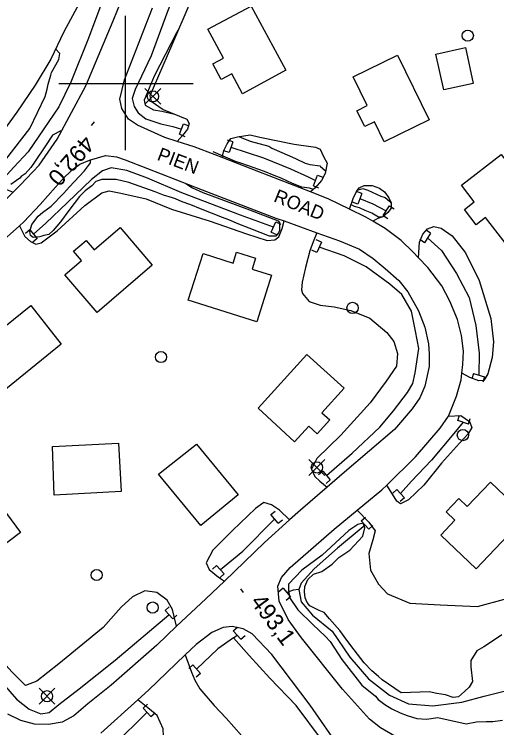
# Model space of a CAD drawing. Extents: x 642515 to 647219, y 6080136 to 6084356.
# Drawn here: x 643780.2 to 643866.3, y 6081485.1 to 6081612.4 of the extents above; entities that cross this region are included whole.
import ezdxf

# ---------------------------------------------------------------- set-up
doc = ezdxf.new("R2010")
doc.units = 0
for name, color, linetype in [('Level 19', 7, 'Continuous'), ('Level 2', 7, 'Continuous'), ('Level 21', 7, 'Continuous'), ('Level 26', 7, 'Continuous'), ('Level 3', 7, 'Continuous'), ('Level 31', 7, 'Continuous'), ('Level 36', 7, 'Continuous'), ('Level 4', 7, 'Continuous'), ('Level 61', 7, 'Continuous')]:
    doc.layers.add(name, color=color, linetype=linetype)

msp = doc.modelspace()

# ---------------------------------------------------------------- linework, layer by layer
at = {"layer": 'Level 19'}
for points in [[(643831.06, 6081654.31), (643831.99, 6081651.64), (643832.31, 6081649.67), (643832.1, 6081648.48), (643831.21, 6081647.66), (643829.54, 6081647.7), (643825.17, 6081648.15), (643822.52, 6081648.29), (643821.82, 6081647.76), (643820.73, 6081646.29), (643818.93, 6081641.16), (643816.67, 6081632), (643814.94, 6081625.17), (643813.39, 6081619.86), (643811.57, 6081614.41), (643808.28, 6081606.76), (643804.43, 6081597.87), (643804.66, 6081596.92), (643806.77, 6081595.44), (643811, 6081593.71), (643811.46, 6081592.93), (643811.16, 6081591.9), (643810.23, 6081590.75), (643809.32, 6081589.72)], [(643799.39, 6081615.12), (643798.24, 6081616.05), (643796.81, 6081616.85), (643795.49, 6081617.32), (643793.8, 6081617.29), (643792.68, 6081616.45), (643791.81, 6081614.33), (643789.04, 6081609.27), (643786.74, 6081604.39), (643783.98, 6081599.77), (643780.67, 6081594.95), (643777.33, 6081590.45), (643775.5, 6081588.27), (643773.83, 6081586.1), (643773.65, 6081585.12), (643774.07, 6081584.3), (643775.32, 6081583.05), (643777.33, 6081581.97), (643778.54, 6081581.29), (643780.02, 6081580.68)], [(643817.3, 6081586.84), (643817.62, 6081588.11), (643818.19, 6081589.28), (643818.87, 6081590.23), (643820.08, 6081590.57), (643822.29, 6081590.9), (643824.06, 6081590.5), (643830.15, 6081589.25), (643833.96, 6081588.71), (643834.81, 6081588.35), (643835.38, 6081587.05), (643836.04, 6081585.87), (643835.7, 6081584.01), (643835.02, 6081582.75), (643833.91, 6081581.45), (643833.11, 6081580.71)], [(643840.02, 6081577.63), (643840.68, 6081579.51), (643841.28, 6081580.8), (643841.79, 6081581.42), (643842.65, 6081581.88), (643844.08, 6081581.84), (643845.42, 6081581.38), (643846.27, 6081580.71), (643847.07, 6081579.63), (643847.45, 6081578.77), (643847.47, 6081577.81), (643846.9, 6081577.02), (643845.98, 6081576.27), (643845.09, 6081575.95), (643844.18, 6081575.49)], [(643781.14, 6081574.67), (643782.11, 6081572.76), (643783.14, 6081571.86), (643784.06, 6081571.36), (643785.05, 6081571.62), (643787.89, 6081573.75), (643792.79, 6081578.31), (643795.87, 6081580.53), (643797.18, 6081580.9), (643799.22, 6081580.47), (643803.73, 6081579.48), (643808.29, 6081577.61), (643815.2, 6081575.48), (643821.69, 6081573.21), (643825.35, 6081572.04), (643826.72, 6081572.13), (643827.45, 6081572.71), (643828.04, 6081574.16), (643828.37, 6081575.53)], [(643852.38, 6081568.97), (643852.52, 6081571.73), (643853.11, 6081573.18), (643853.94, 6081574.12), (643855.12, 6081574.52), (643856.39, 6081574.24), (643858.37, 6081572.88), (643860.75, 6081569.81), (643863.21, 6081564.93), (643865.24, 6081558.09), (643865.71, 6081553.97), (643865.49, 6081551.13), (643864.72, 6081548.26), (643864.03, 6081547.04), (643863.1, 6081547.02), (643861.49, 6081547.6), (643860.08, 6081548.39)], [(643834.23, 6081573.41), (643833.53, 6081571.83), (643832.95, 6081570.22), (643832.22, 6081567.23), (643831.58, 6081564.6), (643831.47, 6081563.26), (643831.64, 6081562.59), (643832.82, 6081561.17), (643834.8, 6081560.5), (643837.32, 6081560.18), (643840.31, 6081559.53), (643843.66, 6081558.18), (643846.73, 6081555.64), (643847.97, 6081554.03), (643848.59, 6081551.89), (643848.42, 6081549.63), (643846.58, 6081546.92), (643843.74, 6081543.06), (643838.47, 6081537.31), (643834.2, 6081533.12), (643833.28, 6081531.2), (643833.84, 6081529.95), (643834.75, 6081529.08), (643836.08, 6081528.04)], [(643857.71, 6081540.71), (643859.89, 6081540.78), (643861.45, 6081539.71), (643861.88, 6081538.65), (643861.23, 6081537.56), (643859.65, 6081535.84), (643856.46, 6081532.28), (643853.29, 6081528.4), (643850.6, 6081525.76), (643849.15, 6081525.06), (643848.48, 6081525.5), (643847.71, 6081526.78), (643846.68, 6081528.4)], [(643829.34, 6081522.18), (643827.53, 6081523.91), (643826.1, 6081524.87), (643824.78, 6081525.26), (643823.24, 6081524.19), (643819.15, 6081520.29), (643815.67, 6081516.76), (643814.45, 6081514.5), (643815.01, 6081513.33), (643816.68, 6081511.94), (643817.71, 6081511.27)], [(643841.43, 6081523.93), (643843.51, 6081521.8), (643844.62, 6081520.22), (643844.2, 6081518.62), (643843.52, 6081516.2), (643843.79, 6081513.23), (643845.21, 6081510.71), (643846.81, 6081509), (643850.79, 6081507.33), (643856.21, 6081507.04), (643862.89, 6081506.72), (643867.72, 6081508.01)], [(643809.2, 6081503.18), (643808.48, 6081506.16), (643807.53, 6081507.83), (643805.66, 6081509.24), (643803.55, 6081509.5), (643801.32, 6081508.42), (643799.27, 6081506.59), (643796.08, 6081502.96), (643788.17, 6081496.5), (643784.22, 6081493.38), (643782.22, 6081492.64), (643779.84, 6081495.02), (643777.02, 6081498.1), (643774.62, 6081499.75), (643773.47, 6081499.48), (643770.5, 6081497.2)], [(643810.74, 6081498.1), (643811.87, 6081495), (643812.45, 6081493.58), (643813.36, 6081492.03), (643815.89, 6081489.05), (643818.06, 6081486.78), (643822.15, 6081482.13)], [(643782.93, 6081478.42), (643781.13, 6081477.13), (643780.07, 6081476.01), (643779.14, 6081474.26), (643778.59, 6081472.16), (643779.01, 6081470.22), (643779.99, 6081468.75), (643781.66, 6081467.29), (643783.9, 6081466.23), (643786.74, 6081466.46), (643789.98, 6081466.8), (643791.83, 6081467.44), (643795.32, 6081468.92), (643800.32, 6081470.59), (643801.97, 6081471.34), (643802.76, 6081472.16), (643803.66, 6081473.71), (643804.94, 6081476.98), (643806.46, 6081479.58), (643806.92, 6081482.27), (643806.79, 6081484.88), (643805.71, 6081487.26), (643804.04, 6081488.65), (643802.26, 6081490.08)]]:
    msp.add_lwpolyline(points, dxfattribs=at)
at = {"layer": 'Level 2'}
for points in [[(643809.7, 6081610.06), (643809.2, 6081609.08), (643805.18, 6081601.37), (643803.42, 6081597.11), (643803.6, 6081596.2), (643805.07, 6081595.37), (643806.57, 6081595.11), (643808.9, 6081594.57)], [(643778.72, 6081586.47), (643782.97, 6081592.02), (643785.76, 6081597.72), (643786.11, 6081599.07), (643786.25, 6081599.92), (643786.75, 6081601.52), (643786.87, 6081602.01), (643788.16, 6081604.35), (643788.33, 6081605.41), (643787.6, 6081606.22)], [(643788.62, 6081591.54), (643788.51, 6081591.62), (643787.07, 6081590.84), (643785.69, 6081588.74), (643783.97, 6081586.17), (643783.16, 6081585.07), (643782.15, 6081583.92), (643781.46, 6081583.47), (643781.2, 6081583.17), (643779.63, 6081582.06)], [(643820.29, 6081590.61), (643820.69, 6081590.45), (643822.3, 6081589.79), (643825.66, 6081588.88), (643826.17, 6081588.51), (643829.36, 6081587.16), (643830.52, 6081586.59), (643832.14, 6081585.85), (643832.97, 6081585.58), (643834.79, 6081585.34), (643834.83, 6081585.3), (643835.78, 6081584.47)], [(643833.59, 6081581.15), (643832.89, 6081581.35), (643831.51, 6081581.58), (643829.86, 6081582.2), (643827.86, 6081583.19), (643826.58, 6081583.63), (643824.88, 6081584.37), (643820.84, 6081585.79), (643819.7, 6081586.12), (643815.71, 6081587.86)], [(643810.82, 6081582.21), (643812.05, 6081581.43), (643813.88, 6081580.58), (643822.21, 6081577.51), (643827.3, 6081575.55), (643827.56, 6081575.25), (643827.58, 6081573.8), (643827.4, 6081573.43), (643826.92, 6081572.79), (643825.75, 6081572.84), (643824.1, 6081573.45), (643822.16, 6081574.25), (643820.3, 6081574.97), (643818.52, 6081575.7), (643817.4, 6081576.15), (643813.47, 6081577.7), (643811.74, 6081578.39), (643810.21, 6081578.97), (643808.97, 6081579.45), (643808.47, 6081579.66), (643806.83, 6081580.12), (643805.38, 6081580.71), (643800.68, 6081582.41), (643798.4, 6081582.9), (643795.86, 6081582.93), (643794.76, 6081582.54), (643794.09, 6081581.77), (643792.86, 6081580.88), (643791.84, 6081579.89), (643790.92, 6081578.66), (643789.96, 6081577.39), (643788.45, 6081575.4), (643787.15, 6081573.83), (643786.39, 6081573.13), (643785.48, 6081572.95), (643784.77, 6081572.67), (643783.61, 6081572.55), (643783.1, 6081572.92), (643782.98, 6081573.63), (643783.33, 6081574.9), (643784.48, 6081576.39), (643785.28, 6081577.04), (643786.81, 6081578.19), (643788.99, 6081580.43), (643790.08, 6081581.59), (643791.8, 6081583.47), (643792.77, 6081584.5), (643793.85, 6081585.9), (643793.83, 6081586.4)], [(643841.49, 6081581.05), (643841.56, 6081581.08), (643842.43, 6081581.3), (643843.33, 6081581.04), (643845.62, 6081579.94), (643846.4, 6081579.71), (643847.17, 6081579.04), (643847.45, 6081578.68)], [(643845.73, 6081576.18), (643845.23, 6081576.21), (643844.02, 6081576.9), (643842.86, 6081577.39), (643841.82, 6081577.84), (643840.92, 6081578.1), (643840.31, 6081578.44)], [(643835.51, 6081505.64), (643834.61, 6081505.98), (643832.94, 6081506.84), (643832.46, 6081507.41), (643832.16, 6081508.27), (643832, 6081509.31), (643832.1, 6081510.28), (643832.61, 6081511.56), (643833.64, 6081512.48), (643835.1, 6081512.94), (643836.94, 6081514.27), (643838.14, 6081515.47), (643840.1, 6081516.77), (643842.43, 6081519.26), (643842.77, 6081520.77), (643842.51, 6081521.6), (643841.52, 6081521.33), (643839.91, 6081520.26), (643835.18, 6081515.88), (643831.54, 6081513.18), (643829.13, 6081510.69), (643829.16, 6081509.69), (643829.34, 6081508.33), (643830.81, 6081506.13), (643833.49, 6081503.49), (643835.68, 6081501.42), (643836.59, 6081500.48), (643838.7, 6081497.28), (643842.23, 6081492.68), (643844.66, 6081490.71), (643845.14, 6081490.13), (643846.37, 6081489.21), (643847.59, 6081488.44), (643849.09, 6081487.74), (643850.33, 6081487.26), (643852.05, 6081486.73), (643853.79, 6081486.64), (643855.78, 6081486.93), (643860.89, 6081485.78), (643862.72, 6081486.14), (643864.44, 6081486.22), (643865.65, 6081486.22), (643867.32, 6081486.41)], [(643867.21, 6081501.66), (643865.55, 6081500.54), (643864.01, 6081499.55), (643862.74, 6081498.79), (643861.69, 6081497.07), (643861.72, 6081495.98), (643861.98, 6081493.34), (643861.41, 6081492.34), (643860.57, 6081491.56), (643859.51, 6081490.6), (643858.56, 6081490.46), (643857.16, 6081490.93), (643855.65, 6081491.19), (643854.26, 6081491.5), (643849.28, 6081491.33), (643845.87, 6081493.64), (643845.23, 6081494.21), (643844.03, 6081495.25), (643842.64, 6081496.69), (643840.88, 6081498.99), (643839.59, 6081500.72), (643838.31, 6081502.44), (643836.48, 6081504.49), (643835.51, 6081505.64)]]:
    msp.add_lwpolyline(points, dxfattribs=at)
at = {"layer": 'Level 21'}
for points in [[(643710.16, 6081521.04), (643716.3, 6081526.08), (643720.63, 6081529.63), (643725.84, 6081533.79), (643733.91, 6081540.23), (643740.4, 6081545.91), (643744.23, 6081549.26), (643747.02, 6081551.59), (643754.73, 6081558), (643758.17, 6081560.87), (643761.09, 6081563.4), (643771.97, 6081572.84), (643773.31, 6081574.14), (643780.02, 6081580.68), (643781.26, 6081581.89), (643784.65, 6081585.5), (643787.85, 6081590.11), (643792.99, 6081599.62), (643797.87, 6081611.24), (643799.39, 6081615.12)], [(643827.27, 6081510.34), (643827.89, 6081511.91), (643829.43, 6081513.67), (643837.32, 6081520.52), (643841.43, 6081523.93), (643845.8, 6081527.54), (643846.68, 6081528.4), (643851.82, 6081533.46), (643856.25, 6081538.52), (643857.71, 6081540.71), (643859.13, 6081544.23), (643859.95, 6081547.15), (643860.08, 6081548.39), (643860.25, 6081549.91), (643860.37, 6081552.3), (643860.03, 6081555.1), (643859.32, 6081557.92), (643857.97, 6081561.21), (643856.5, 6081563.94), (643854.03, 6081567.24), (643852.38, 6081568.97), (643851.43, 6081569.98), (643849.28, 6081572.01), (643846.43, 6081574.2), (643844.18, 6081575.49), (643842.95, 6081576.19), (643840.02, 6081577.63), (643836.24, 6081579.5), (643833.11, 6081580.71), (643823.86, 6081584.28), (643817.3, 6081586.84), (643812.35, 6081588.77), (643809.32, 6081589.72), (643807.07, 6081590.43), (643802.2, 6081592.65), (643800.6, 6081593.68), (643799.43, 6081595.62), (643799.07, 6081597.29), (643799.89, 6081600.73), (643804.86, 6081613.58)], [(643777.23, 6081571.2), (643781.14, 6081574.67), (643781.91, 6081575.36), (643784.85, 6081578.46), (643787.55, 6081581.55), (643789.28, 6081583.44), (643790.8, 6081584.83), (643791.92, 6081585.67), (643793.65, 6081586.35), (643796.5, 6081587.19), (643798.45, 6081586.99), (643800.01, 6081586.45), (643803.99, 6081584.86), (643813.76, 6081581.07), (643826.92, 6081576.05), (643828.37, 6081575.53), (643834.23, 6081573.41), (643838.25, 6081571.96), (643841.81, 6081570.5), (643844.26, 6081568.81), (643846.43, 6081567.06), (643848.84, 6081564.88), (643850.46, 6081562.85), (643852.38, 6081559.51), (643853.5, 6081556.56), (643854.14, 6081553.58), (643854.26, 6081551.81), (643854.24, 6081549.55), (643853.51, 6081546.03), (643852.6, 6081543.95), (643851.24, 6081541.97), (643848.05, 6081538.33), (643839.16, 6081530.68), (643836.08, 6081528.04), (643831.3, 6081523.94), (643829.34, 6081522.18), (643824.87, 6081518.15), (643817.71, 6081511.27), (643814.41, 6081508.1), (643809.2, 6081503.18), (643805.65, 6081499.82), (643797.5, 6081492.67), (643793.36, 6081489.33), (643790.84, 6081487.23), (643788.79, 6081486.08), (643786.36, 6081485.64), (643783.85, 6081485.71), (643781.4, 6081486.36), (643779.1, 6081487.53)], [(643872.1, 6081481.95), (643864.54, 6081481.16), (643857.81, 6081481.24), (643852.11, 6081482.07), (643848.14, 6081483.58), (643845.58, 6081485.06), (643843.63, 6081486.62), (643838.8, 6081491.99), (643831.46, 6081501.14), (643829.11, 6081504.41), (643827.52, 6081507.69), (643827.27, 6081510.34)], [(643838.53, 6081481.14), (643833.04, 6081489.12), (643826.2, 6081498.14), (643822.69, 6081501.82), (643821.06, 6081502.72), (643819.1, 6081503.15), (643817.5, 6081502.97), (643815.46, 6081502.1), (643812.66, 6081499.94), (643810.74, 6081498.1), (643804.17, 6081491.8), (643802.26, 6081490.08), (643795.65, 6081484.14)]]:
    msp.add_lwpolyline(points, dxfattribs=at)
at = {"layer": 'Level 26'}
for p, q in [((643809.72, 6081590.99), (643810.44, 6081592.89)), ((643810.44, 6081592.89), (643811.38, 6081592.51)), ((643809.72, 6081590.99), (643810.66, 6081590.63)), ((643819.23, 6081589.62), (643818.29, 6081589.96)), ((643819.23, 6081589.62), (643818.55, 6081587.72)), ((643818.55, 6081587.72), (643817.61, 6081588.06)), ((643833.62, 6081581.8), (643834.36, 6081583.68)), ((643834.36, 6081583.68), (643835.28, 6081583.32)), ((643833.62, 6081581.8), (643834.54, 6081581.44)), ((643842.26, 6081580.45), (643841.32, 6081580.81)), ((643842.26, 6081580.45), (643841.54, 6081578.55)), ((643841.54, 6081578.55), (643840.6, 6081578.91)), ((643846.06, 6081576.52), (643847.16, 6081578.22)), ((643847.16, 6081578.22), (643848, 6081577.68)), ((643846.06, 6081576.52), (643846.9, 6081575.98)), ((643826.08, 6081573.51), (643826.88, 6081575.37)), ((643826.88, 6081575.37), (643827.8, 6081574.97)), ((643783, 6081573.92), (643782.24, 6081573.3)), ((643783, 6081573.92), (643784.3, 6081572.38)), ((643826.08, 6081573.51), (643827, 6081573.11)), ((643854.52, 6081573.33), (643853.42, 6081571.63)), ((643854.52, 6081573.33), (643853.7, 6081573.87)), ((643784.3, 6081572.38), (643783.52, 6081571.74)), ((643835.02, 6081571.77), (643834.1, 6081572.17)), ((643835.02, 6081571.77), (643834.22, 6081569.91)), ((643853.42, 6081571.63), (643852.58, 6081572.19)), ((643834.22, 6081569.91), (643833.3, 6081570.31)), ((643862.18, 6081548.33), (643861.88, 6081547.37)), ((643862.18, 6081548.33), (643864.12, 6081547.73)), ((643864.12, 6081547.73), (643863.82, 6081546.77)), ((643859.35, 6081539.93), (643859.65, 6081540.89)), ((643861.25, 6081539.29), (643859.35, 6081539.93)), ((643861.25, 6081539.29), (643861.57, 6081540.25)), ((643835.28, 6081530.85), (643834.52, 6081530.19)), ((643835.28, 6081530.85), (643836.62, 6081529.33)), ((643836.62, 6081529.33), (643835.86, 6081528.67)), ((643848.51, 6081527.63), (643847.75, 6081526.97)), ((643848.51, 6081527.63), (643849.85, 6081526.13)), ((643849.85, 6081526.13), (643849.11, 6081525.47)), ((643826, 6081523.11), (643826.76, 6081523.75)), ((643827.3, 6081521.57), (643826, 6081523.11)), ((643827.3, 6081521.57), (643828.06, 6081522.21)), ((643842.13, 6081522.02), (643842.87, 6081522.68)), ((643843.49, 6081520.52), (643842.13, 6081522.02)), ((643843.49, 6081520.52), (643844.23, 6081521.18)), ((643816.33, 6081514.04), (643815.59, 6081513.36)), ((643816.33, 6081514.04), (643817.69, 6081512.54)), ((643817.69, 6081512.54), (643816.95, 6081511.88)), ((643828.2, 6081509.98), (643827.44, 6081509.34)), ((643828.2, 6081509.98), (643829.5, 6081508.44)), ((643829.5, 6081508.44), (643828.74, 6081507.8)), ((643807.15, 6081505.99), (643807.89, 6081506.65)), ((643808.49, 6081504.49), (643807.15, 6081505.99)), ((643808.49, 6081504.49), (643809.25, 6081505.15)), ((643819.31, 6081502.37), (643820.07, 6081503.03)), ((643820.65, 6081500.87), (643819.31, 6081502.37)), ((643820.65, 6081500.87), (643821.41, 6081501.53)), ((643812.11, 6081496.29), (643811.35, 6081495.63)), ((643812.11, 6081496.29), (643813.45, 6081494.77)), ((643813.45, 6081494.77), (643812.69, 6081494.11)), ((643803.24, 6081488.6), (643804, 6081489.26)), ((643804.58, 6081487.1), (643803.24, 6081488.6)), ((643804.58, 6081487.1), (643805.34, 6081487.76))]:
    msp.add_line(p, q, dxfattribs=at)
at = {"layer": 'Level 3'}
for p, q in [((643794.49, 6081593.2), (643793.96, 6081592.59)), ((643820.58, 6081509.87), (643821.05, 6081509.23))]:
    msp.add_line(p, q, dxfattribs=at)
at = {"layer": 'Level 31'}
for points in [[(643822.49, 6081613.84), (643828.69, 6081602.45), (643820.95, 6081598.24), (643819.02, 6081601.79), (643817.17, 6081600.78), (643815.66, 6081603.56), (643817.57, 6081604.61), (643814.78, 6081609.74), (643822.49, 6081613.84)], [(643856.86, 6081598.92), (643855.47, 6081605.31), (643860.75, 6081606.46), (643862.14, 6081600.07), (643856.86, 6081598.92)], [(643848.61, 6081605.12), (643854.26, 6081593.57), (643846.25, 6081589.65), (643844.51, 6081593.22), (643842.75, 6081592.36), (643841.36, 6081595.21), (643843.21, 6081596.12), (643840.72, 6081601.22), (643848.61, 6081605.12)], [(643867.08, 6081587.38), (643875.01, 6081577.19), (643867.84, 6081571.6), (643864.31, 6081576.14), (643862.66, 6081574.86), (643860.55, 6081577.58), (643862.31, 6081578.95), (643860, 6081581.91), (643867.08, 6081587.38)], [(643804.84, 6081567.64), (643795.03, 6081559.19), (643789.25, 6081565.9), (643792.21, 6081568.46), (643790.79, 6081570.11), (643793.03, 6081572.05), (643794.47, 6081570.37), (643799.11, 6081574.37), (643804.84, 6081567.64)], [(643823.48, 6081557.5), (643811.28, 6081561.39), (643813.94, 6081569.73), (643819.28, 6081568.02), (643819.9, 6081569.95), (643823.28, 6081568.87), (643822.66, 6081566.95), (643826.15, 6081565.83), (643823.48, 6081557.5)], [(643788.61, 6081553.54), (643778.7, 6081545.48), (643773.16, 6081552.31), (643775.87, 6081554.51), (643774.54, 6081556.15), (643777.19, 6081558.3), (643778.51, 6081556.68), (643783.16, 6081560.46), (643788.61, 6081553.54)], [(643823.73, 6081542.12), (643832.44, 6081551.72), (643839.1, 6081545.67), (643835.13, 6081541.3), (643836.54, 6081540.01), (643834.3, 6081537.53), (643832.77, 6081538.92), (643830.21, 6081536.1), (643823.73, 6081542.12)], [(643787.05, 6081535.25), (643798.84, 6081535.89), (643799.32, 6081527.24), (643787.37, 6081526.59), (643787.05, 6081535.25)], [(643812.73, 6081535.7), (643820.17, 6081526.62), (643813.5, 6081521.16), (643805.97, 6081530.35), (643812.73, 6081535.7)], [(643871.57, 6081522.86), (643862.63, 6081513.47), (643856.33, 6081519.46), (643858.86, 6081522.12), (643857.27, 6081523.63), (643859.54, 6081526.02), (643861.06, 6081524.58), (643865.21, 6081528.93), (643871.57, 6081522.86)], [(643766.68, 6081519.82), (643776.1, 6081526.92), (643781.36, 6081519.94), (643771.95, 6081512.85), (643766.68, 6081519.82)]]:
    msp.add_lwpolyline(points, dxfattribs=at)
at = {"layer": 'Level 36'}
for p, q in [((643806.36, 6081596.35), (643803.54, 6081599.17)), ((643803.54, 6081596.35), (643806.36, 6081599.17)), ((643835.63, 6081530.12), (643832.81, 6081532.94)), ((643832.81, 6081530.12), (643835.63, 6081532.94)), ((643787.48, 6081489.3), (643784.66, 6081492.12)), ((643784.66, 6081489.3), (643787.48, 6081492.12))]:
    msp.add_line(p, q, dxfattribs=at)
for centre in [(643861.15, 6081608.6), (643804.95, 6081597.76), (643840.58, 6081560.01), (643806.4, 6081551.24), (643860.27, 6081537.3), (643834.22, 6081531.53), (643794.92, 6081512.34), (643804.92, 6081506.53), (643786.07, 6081490.71)]:
    msp.add_circle(centre, 1, dxfattribs=at)
at = {"layer": 'Level 4'}
for points in [[(643830.95, 6081650.69), (643826.31, 6081651.46), (643822.62, 6081651.99), (643820.74, 6081651.44), (643819.84, 6081650.25), (643818.81, 6081647.64), (643817.41, 6081643.22), (643815.06, 6081635.42), (643812.95, 6081627.48), (643810.68, 6081620.9), (643807.57, 6081612.93), (643804.66, 6081605.02), (643801.79, 6081598.98), (643801.29, 6081597.37), (643801.63, 6081595.94), (643802.31, 6081594.81), (643803.71, 6081593.73), (643806.35, 6081592.86), (643808.52, 6081592.4), (643810.08, 6081591.93)], [(643796.37, 6081616.01), (643793.45, 6081608.18), (643790.34, 6081600.3), (643788.16, 6081595.91), (643785.52, 6081591.94), (643782.72, 6081587.87), (643780.16, 6081585.12), (643777.84, 6081582.58)], [(643818.89, 6081588.68), (643824.71, 6081586.77), (643829.52, 6081584.83), (643832.65, 6081583.38), (643833.98, 6081582.74)], [(643826.48, 6081574.43), (643820.57, 6081576.58), (643810.13, 6081580.57), (643804.02, 6081583.19), (643800.3, 6081584.56), (643797.52, 6081585.02), (643795.99, 6081584.47), (643794.03, 6081582.93), (643789.7, 6081578.85), (643785.86, 6081575.16), (643783.64, 6081573.16)], [(643841.9, 6081579.51), (643844.18, 6081578.58), (643846.6, 6081577.36)], [(643853.98, 6081572.49), (643856.47, 6081570.23), (643859.16, 6081566.13), (643861.38, 6081561.84), (643862.56, 6081556.87), (643863.17, 6081551.94), (643863.14, 6081548.03)], [(643835.94, 6081530.09), (643840.52, 6081534.11), (643845.46, 6081538.71), (643847.89, 6081541.66), (643850.37, 6081544.93), (643851.36, 6081546.49), (643851.76, 6081548.41), (643852.4, 6081552.78), (643851.83, 6081555.85), (643851.11, 6081559.43), (643849.38, 6081562.38), (643847.24, 6081564.26), (643843.04, 6081567.33), (643839.12, 6081569.33), (643834.62, 6081570.85)], [(643860.31, 6081539.61), (643858.67, 6081537.57), (643854.7, 6081532.86), (643851.12, 6081529.11), (643849.17, 6081526.89)], [(643817.01, 6081513.3), (643821.03, 6081516.59), (643826.66, 6081522.33)], [(643842.81, 6081521.26), (643837.92, 6081517.14), (643833.72, 6081513.47), (643831.39, 6081510.9), (643830.98, 6081509.74), (643831.41, 6081507.55), (643833.42, 6081505.18), (643836.96, 6081502.31), (643840.09, 6081497.67), (643843.45, 6081493.81), (643847.2, 6081490.91), (643850.57, 6081489.32), (643854.91, 6081489), (643860.08, 6081489.63), (643864.09, 6081490.74), (643869.57, 6081492.08)], [(643830.98, 6081509.74), (643829.98, 6081509.63), (643828.84, 6081509.22)], [(643773.62, 6081498.11), (643777.41, 6081493.81), (643780.6, 6081490.19), (643782.89, 6081488.4), (643784.96, 6081487.57), (643786.44, 6081487.79), (643788.2, 6081489.2), (643791.81, 6081492.02), (643798.2, 6081497.17), (643807.83, 6081505.23)], [(643819.34, 6081501.12), (643819.99, 6081501.61)], [(643830.97, 6081408.36), (643833.64, 6081411.24), (643836.18, 6081414.22), (643838.67, 6081418.54), (643840.11, 6081421.82), (643841.09, 6081426.4), (643841.89, 6081431.45), (643842.15, 6081437.19), (643841.9, 6081444.06), (643841.32, 6081451.6), (643841.3, 6081457.36), (643841.32, 6081463.85), (643840.8, 6081469.22), (643840.55, 6081473), (643838.59, 6081477.14), (643835.23, 6081482.73), (643830.54, 6081489.03), (643825.82, 6081493.92), (643822.13, 6081497.99), (643819.34, 6081501.12), (643816.56, 6081499.16), (643812.77, 6081495.53)], [(643803.92, 6081487.84), (643797.9, 6081481.91), (643793.64, 6081477.47), (643791.21, 6081475.14), (643789.52, 6081473.89), (643787.55, 6081473.2), (643785.07, 6081472.95), (643783.33, 6081472.96), (643781.98, 6081473.31), (643780.24, 6081473.48)]]:
    msp.add_lwpolyline(points, dxfattribs=at)
at = {"layer": 'Level 61'}
for p, q in [((643800, 6081612.16), (643800, 6081588.16)), ((643812.16, 6081600), (643788.16, 6081600))]:
    msp.add_line(p, q, dxfattribs=at)

# ---------------------------------------------------------------- texts
at = {"layer": 'Level 21'}
for s, rotation, p in [('PIEN', 339.2438, (643805.55, 6081586.48)), ('ROAD', 337.8205, (643826.35, 6081579.06))]:
    msp.add_text(s, height=2.4, rotation=rotation, dxfattribs=at).set_placement(p)
at = {"layer": 'Level 3'}
for s, rotation, p in [('492,0', 229.2054, (643792.57, 6081591.04)), ('493,1', 306.5486, (643822.26, 6081507.54))]:
    msp.add_text(s, height=3, rotation=rotation, dxfattribs=at).set_placement(p)

doc.saveas('drawing.dxf')
